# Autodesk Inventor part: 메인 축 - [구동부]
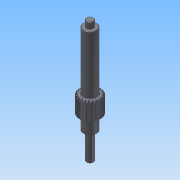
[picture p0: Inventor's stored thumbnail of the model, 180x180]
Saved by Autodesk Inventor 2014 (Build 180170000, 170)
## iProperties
Created: 2016-02
Part Number: 메인 축 - [구동부]
Material: 강철, 연강
Document SubType Name: Modeling
Categories: <?xml version="1.0" encoding="UTF-16"?> <MemberInstance><Categories><FamilyTemplate><FamilyTemplateParameter ValueType="xs:double" Id="1" ObjectReferenceKey="da
Density: 7.86 g/cm^3
Mass: 187.503 g
Surface Area: 82.0529 cm^2
Volume: 23.8554 cm^3
Appearance: 강철
Author: mdu
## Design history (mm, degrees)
sketch "Sketch1"
  geometry: C1 r 12 at (0, 0)
  constraints: 1 centre point
  dimensions: "d0" = 24 diameter of C1 (= da_da)
extrude "Extrusion1" new body sketch "Sketch1" distance "d1" = 20 (= da_b); taper "d2" = 0 deg
workplane "Work Plane2"
feature "피치 지름" dims "d4" = 10, "d5" = 0
workplane "Work Plane8"
workplane "Work Plane9"
chamfer "모따기1" distance "d49" = 1; stored, may be unused: second distance "d50" = 2, angle "d51" = 45 deg
sketch "스케치3"
  geometry: C1 r 7.5 at (0, 0); 1 further point
  constraints: 1 centre point, 1 coincident
  dimensions: "d52" = 15 diameter of C1
extrude "돌출2" join sketch "스케치3" distance "d53" = 66; taper "d54" = 0 deg
sketch "스케치4"
  geometry: C1 r 4 at (0, 0); 1 further point
  constraints: 1 centre point, 1 coincident
  dimensions: "d55" = 8 diameter of C1
extrude "돌출3" join sketch "스케치4" distance "d56" = 7; taper "d57" = 0 deg
sketch "스케치5"
  geometry: C1 r 7.5 at (0, 0) reference; C2 r 7.5 at (0, 0) reference; 1 further point
extrude "돌출4" join sketch "스케치5" distance "d62" = 16; taper "d63" = 0 deg
sketch "스케치6"
  geometry: C1 r 4 at (0, 0); 1 further point
  constraints: 1 centre point, 1 coincident
  dimensions: "d64" = 8 diameter of C1
extrude "돌출5" join sketch "스케치6" distance "d65" = 30; taper "d66" = 0 deg
chamfer "모따기2" distance "d58" = 0.5; stored, may be unused: second distance "d59" = 2, angle "d60" = 45 deg
fillet "모깎기1" dims "d61" = 0.5
feature "스퍼 기어" dims "da_b" = 20, "da_d" = 22, "da_aw" = 31, "da_da" = 24, "da_df" = 19.5, "da_dw" = 22, angle "da_beta" = 0 deg, "da_lefttooth" = 0, "da_righttooth" = 0
sketch "스케치7" dims "d68" = 18
  geometry: C1 r 0.25 at (0, -9); 2 further points
  constraints: 2 vertical alignment, 1 centre point, 1 coincident, 2 other
  dimensions: "d67" = 0.5 diameter of C1
extrude "돌출6" join sketch "스케치7" distance "d69" = 0.3; taper "d70" = 0 deg
body "Solid1"
sketch "Sketch2"
  geometry: C1 r 12 at (0, 0) reference; C2 r 11 at (0, 0)
  constraints: 1 centre point, 1 coincident
  dimensions: "d3" = 22 diameter of C2 (= da_dw)
body "Srf1"
node "투영된 루프1"
other parameters: "d16" = 31 (= da_aw), "d17" = 0, "d34" = 1.428 (computed from da_z), "d39" = 0, "d41" = 0, "d43" = 31 (= da_aw), "d46" = 31 (= da_aw), "d47" = 0, "d48" = 0
